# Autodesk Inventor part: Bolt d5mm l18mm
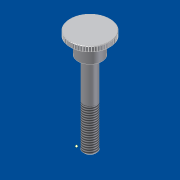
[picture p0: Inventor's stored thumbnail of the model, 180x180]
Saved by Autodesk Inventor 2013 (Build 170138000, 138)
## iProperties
Shininess: 64.0
Length Units: 11269
Angle Units: 11279
Time Units: 11290
Mass Units: 11283
Length Display Precision: 3
Angle Display Precision: 2
Compacted: True
Part Number: Bolt d5mm l18mm
Document SubType Name: Modellieren
Created: 2001-04
Material: Standard
Designer: dl
Density: 1 g/cm^3
Density: 0.0
Volumn: 0.0
Area: 0.0
PropertySet Name: Model Information
Control State: 0
Master: False
Checked Out: False
Author: dl
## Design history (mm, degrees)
derived "Bolzen.ipt"
body "Solid1"
tag "TaggingFeature2"
feature "DerivedBody::Bolzen.ipt"
other parameters: "d30" = 0
